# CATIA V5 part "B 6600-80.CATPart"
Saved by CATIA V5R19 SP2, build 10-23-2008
Part number: B 6600-80
Bounding box of the stored display mesh (mm): x -59.975 to 59.975, y -59.975 to 59.975, z 0 to 300
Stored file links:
  C:\Users\Bora\Desktop\3D Katı model\B serisi\B 6600\B 6600-80.CATPart
  C:\Program Files\Dassault Systemes\B19\intel_a\reffiles\standard\MetricThickPitch.txt
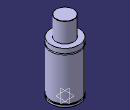
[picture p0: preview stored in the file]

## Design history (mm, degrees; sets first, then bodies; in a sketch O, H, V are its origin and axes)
Body1 (main body)
  Sketch1 on yz-plane, origin (0, 0, 0), H (0, 1, 0), V (0, 0, 1)
    point P3 (37.5, 299)
    point P5 (37.5, 299)
    point P10 (60, 192)
    point P11 (60, 197)
    point P13 (60, 197)
    point P14 (60, 192)
    line L1 (60, 0) -> (60, 8)
    line L2 (37.5, 299) -> (37.5, 217)
    arc A1 centre (36.5, 299) radius 1 from (37.5, 299) to (36.5, 300) ccw
    line L3 (56, 13) -> (56, 8)
    line L4 (60, 13) -> (60, 192)
    line L5 (60, 197) -> (60, 217)
    arc A2 centre (60, 194.5) radius 2.5 from (60, 197) to (60, 192) ccw
    line L6 (36.5, 300) -> (0, 300)
    point P15 (0, 300)
    line L7 (37.5, 217) -> (60, 217)
    line L8 (0, 0) -> (60, 0)
    line L9 (56, 13) -> (60, 13)
    line L10 (56, 8) -> (60, 8)
    coincidence: P15 V, P3 P5, P10 P14, P11 P13
    tangency: L6 A1
    horizontal: L7 H, L8 H, L9 H, L10 H
  Shaft1: profile Sketch1, axis Sketch1.V, angle 360
  Sketch2 on face of Shaft1 from Sketch1.L8, origin (0, 0, 0), H (1, 0, 0), V (0, -1, 0)
    point P1 (40, 0)
    distance P1 V = 40
  Hole1: placed by Sketch2, at (40, 0, 0) direction (0, 0, 1), diameter 8.376, depth 16, threaded "M10", thread diameter 10, thread depth 16, pitch 1.5
  CircPattern1: of Hole1, instances 4, angular step 90, axis from xy-plane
